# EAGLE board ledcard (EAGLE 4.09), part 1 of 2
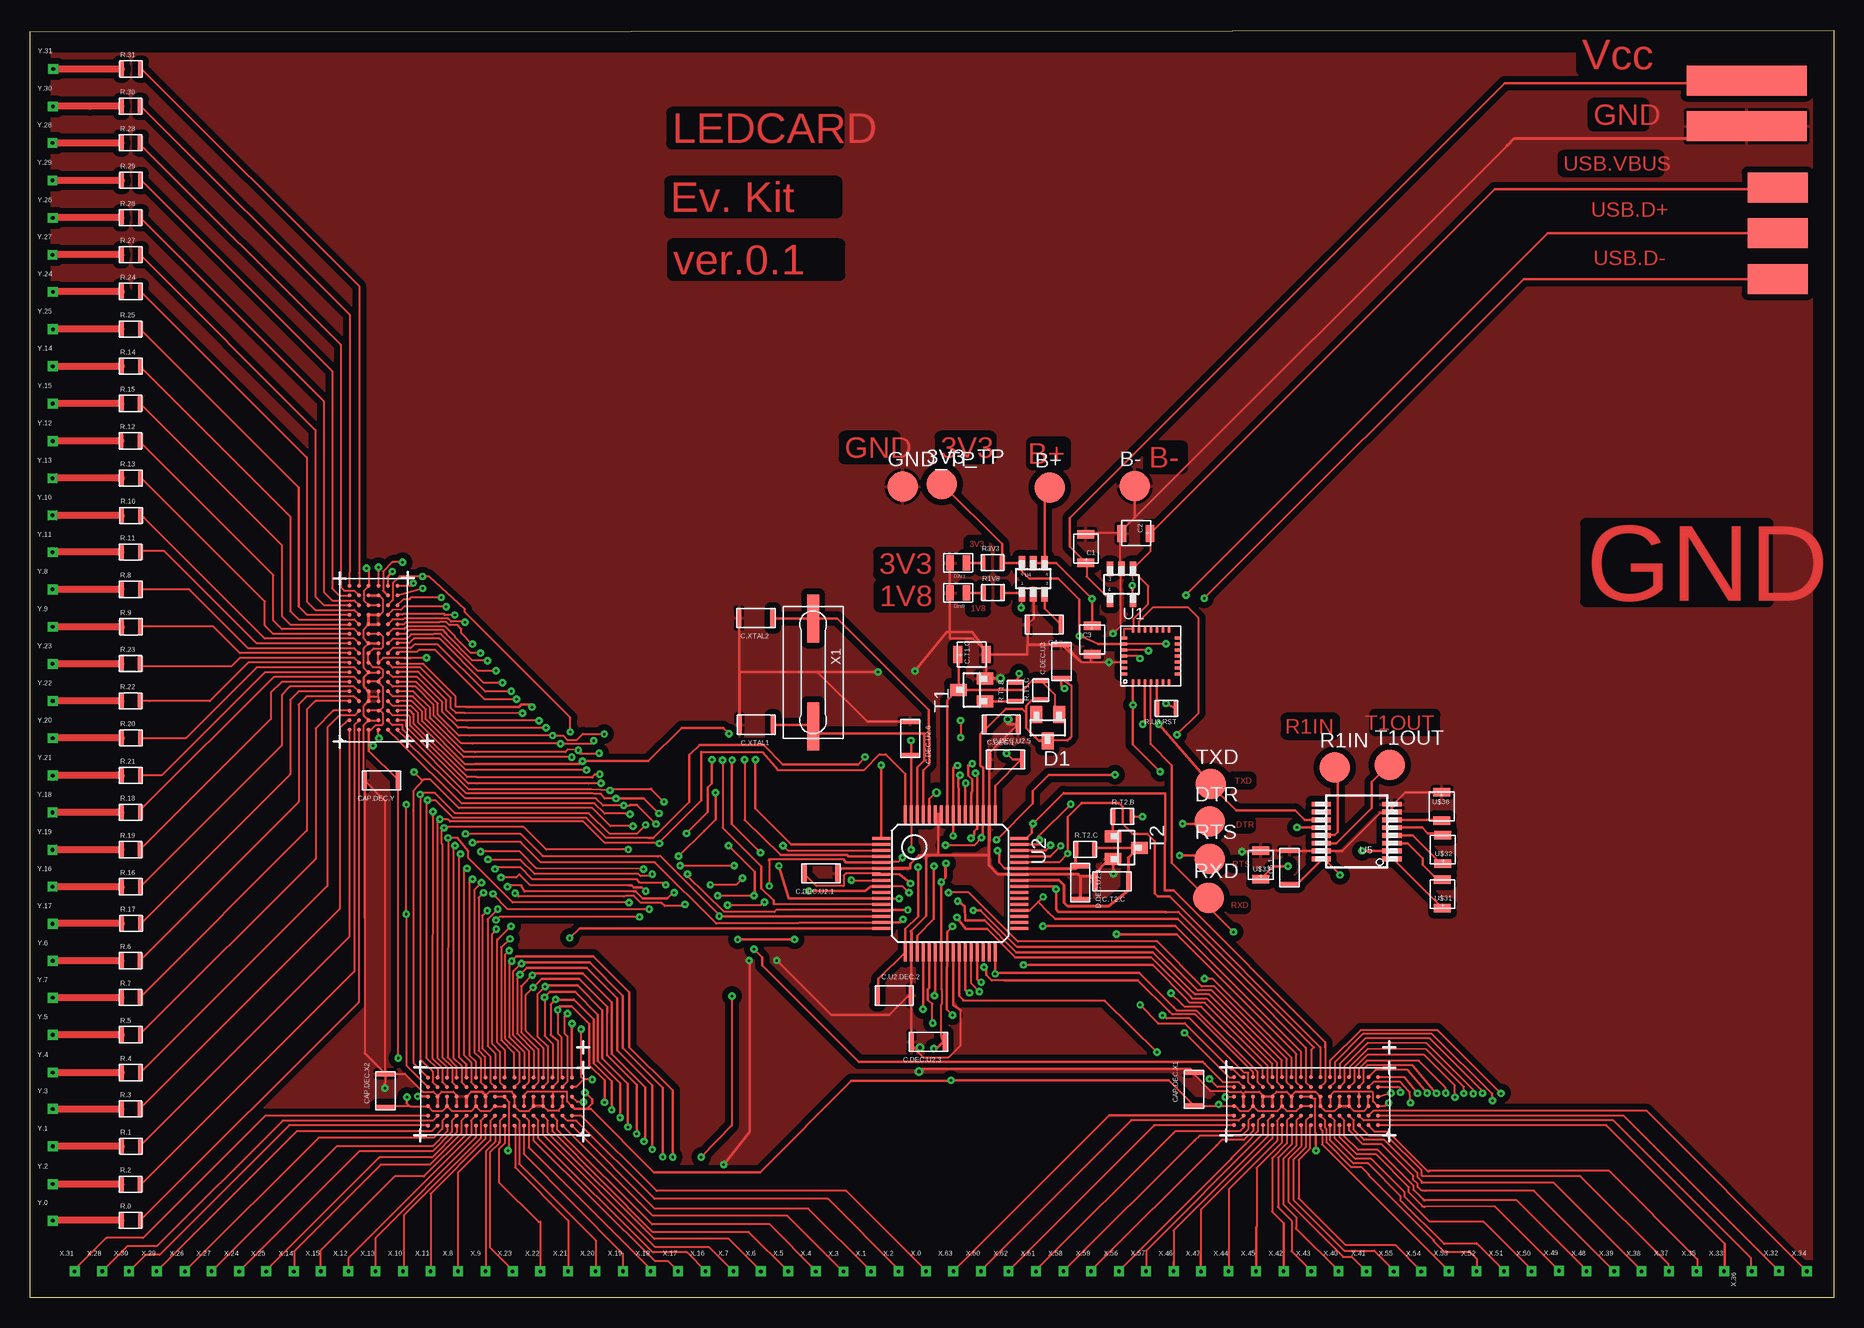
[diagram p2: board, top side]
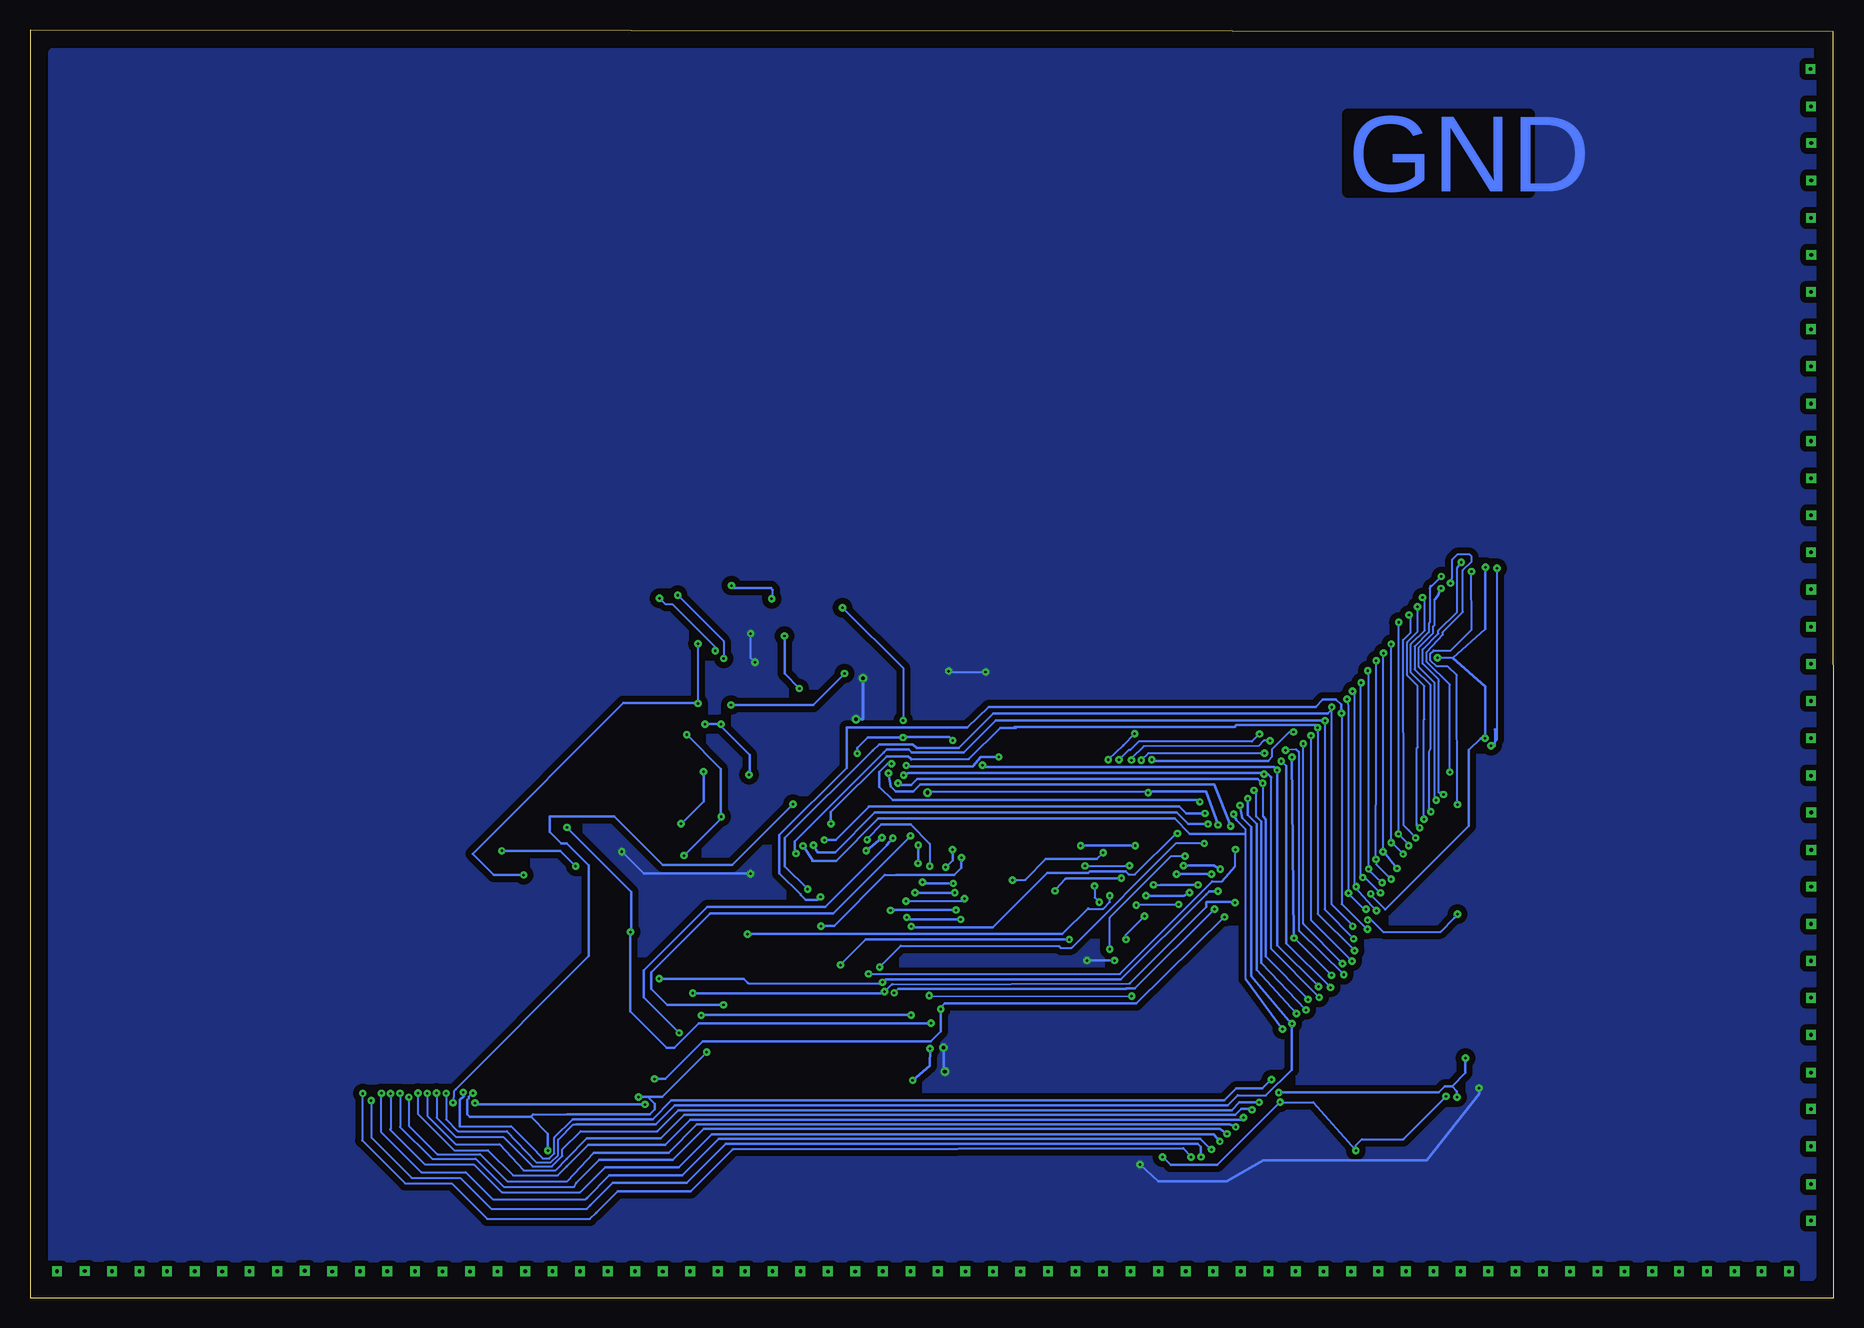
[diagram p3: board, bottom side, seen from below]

Size 150.31 x 105.7 mm. Coordinates in mm from the lower left corner, seen from the top.
Outline: 150.31,0 0,0.01 0.03,105.57 150.31,105.7 150.31,0
Copper layers used: Top, Bottom

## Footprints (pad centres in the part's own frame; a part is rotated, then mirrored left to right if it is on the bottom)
B2,54 = smd 2.54 x 2.54: PP 0,0
CAP_A = smd 1.422 x 0.711: N 0.045,-1.13; P 0.045,1.245
CAP_CERAMIC = smd 1.6 x 0.4: P$1 0,1.22; P$2 0,-1.58
SOT23 = smd 1 x 1.4: 1 -0.95,-1.1; 2 0.95,-1.1; 3 0,1.1
LED_0603 = smd 1.27 x 0.635: P$A 0,-0.7; P$K 0,0.7
USB_CON = smd 5 x 2.5: P$D+ -2.54,1.27; P$D- -2.54,-2.54; P$VCC -2.54,-6.35
SMDR = smd 1.25 x 0.4: P$1 0,0.73; P$2 0,-0.87
SOT23-5 = smd 0.55 x 1.2: 1 -0.95,-1.3; 2 0,-1.3; 3 0.95,-1.3; 4 0.95,1.3; 5 -0.95,1.3
TQFP64 = smd 0.25 x 1.5: 1 -3.75,-5.75; 2 -3.25,-5.75; 3 -2.75,-5.75; 4 -2.25,-5.75; 5 -1.75,-5.75; 6 -1.25,-5.75; 7 -0.75,-5.75; 8 -0.25,-5.75; 9 0.25,-5.75; 10 0.75,-5.75; 11 1.25,-5.75; 12 1.75,-5.75; 13 2.25,-5.75; 14 2.75,-5.75; 15 3.25,-5.75; 16 3.75,-5.75; 33 3.75,5.75; 34 3.25,5.75; 35 2.75,5.75; 36 2.25,5.75; 37 1.75,5.75; 38 1.25,5.75; 39 0.75,5.75; 40 0.25,5.75; 41 -0.25,5.75; 42 -0.75,5.75; 43 -1.25,5.75; 44 -1.75,5.75; 45 -2.25,5.75; 46 -2.75,5.75; 47 -3.25,5.75; 48 -3.75,5.75 | smd 1.5 x 0.25: 17 5.75,-3.75; 18 5.75,-3.25; 19 5.75,-2.75; 20 5.75,-2.25; 21 5.75,-1.75; 22 5.75,-1.25; 23 5.75,-0.75; 24 5.75,-0.25; 25 5.75,0.25; 26 5.75,0.75; 27 5.75,1.25; 28 5.75,1.75; 29 5.75,2.25; 30 5.75,2.75; 31 5.75,3.25; 32 5.75,3.75; 49 -5.75,3.75; 50 -5.75,3.25; 51 -5.75,2.75; 52 -5.75,2.25; 53 -5.75,1.75; 54 -5.75,1.25; 55 -5.75,0.75; 56 -5.75,0.25; 57 -5.75,-0.25; 58 -5.75,-0.75; 59 -5.75,-1.25; 60 -5.75,-1.75; 61 -5.75,-2.25; 62 -5.75,-2.75; 63 -5.75,-3.25; 64 -5.75,-3.75
MLP-28 = smd 0.55 x 0.23: P$1 -2.25,-1.5; P$2 -2.25,-1; P$3 -2.25,-0.5; P$4 -2.25,0; P$5 -2.25,0.5; P$6 -2.25,1; P$7 -2.25,1.5; P$15 2.25,1.5; P$16 2.25,1; P$17 2.25,0.5; P$18 2.25,0; P$19 2.25,-0.5; P$20 2.25,-1; P$21 2.25,-1.5 | smd 0.23 x 0.55: P$8 -1.5,2.25; P$9 -1,2.25; P$10 -0.5,2.25; P$11 0,2.25; P$12 0.5,2.25; P$13 1,2.25; P$14 1.5,2.25; P$22 1.5,-2.25; P$23 1,-2.25; P$24 0.5,-2.25; P$25 0,-2.25; P$26 -0.5,-2.25; P$27 -1,-2.25; P$28 -1.5,-2.25
SOT-23_RT6 = smd 0.55 x 1.2: 1 -0.95,-1.3; 2 0,-1.3; 3 0.95,-1.3; 4 0.95,1.3; 5 0,1.3; 6 -0.95,1.3
TSOP16 = smd 0.4 x 1.6: 1 -2.275,-2.79; 2 -1.625,-2.79; 3 -0.975,-2.79; 4 -0.325,-2.79; 5 0.325,-2.79; 6 0.975,-2.79; 7 1.625,-2.79; 8 2.275,-2.79; 9 2.275,3.11; 10 1.625,3.11; 11 0.975,3.11; 12 0.325,3.11; 13 -0.325,3.11; 14 -0.975,3.11; 15 -1.625,3.11; 16 -2.275,3.11
PIN2 = smd 10 x 2.5: P$1 1.27,0; P$2 1.27,-3.81
LFBGA96 = smd 0.35 x 0.35: P$A1 -2,-6.054; P$A2 -1.2,-6.054; P$A3 -0.4,-6.054; P$A4 0.4,-6.054; P$A5 1.2,-6.054; P$A6 2,-6.054; P$B1 -2,-5.254; P$B2 -1.2,-5.254; P$B3 -0.4,-5.254; P$B4 0.4,-5.254; P$B5 1.2,-5.254; P$B6 2,-5.254; P$C1 -2,-4.454; P$C2 -1.2,-4.454; P$C3 -0.4,-4.454; P$C4 0.4,-4.454; P$C5 1.2,-4.454; P$C6 2,-4.454; P$D1 -2,-3.654; P$D2 -1.2,-3.654; P$D3 -0.4,-3.654; P$D4 0.4,-3.654; P$D5 1.2,-3.654; P$D6 2,-3.654; P$E1 -2,-2.854; P$E2 -1.2,-2.854; P$E3 -0.4,-2.854; P$E4 0.4,-2.854; P$E5 1.2,-2.854; P$E6 2,-2.854; P$F1 -2,-2.054; P$F2 -1.2,-2.054; P$F3 -0.4,-2.054; P$F4 0.4,-2.054; P$F5 1.2,-2.054; P$F6 2,-2.054; P$G1 -2,-1.254; P$G2 -1.2,-1.254; P$G3 -0.4,-1.254; P$G4 0.4,-1.254; P$G5 1.2,-1.254; P$G6 2,-1.254; P$H1 -2,-0.454; P$H2 -1.2,-0.454; P$H3 -0.4,-0.454; P$H4 0.4,-0.454; P$H5 1.2,-0.454; P$H6 2,-0.454; P$J1 -2,0.346; P$J2 -1.2,0.346; P$J3 -0.4,0.346; P$J4 0.4,0.346; P$J5 1.2,0.346; P$J6 2,0.346; P$K1 -2,1.146; P$K2 -1.2,1.146; P$K3 -0.4,1.146; P$K4 0.4,1.146; P$K5 1.2,1.146; P$K6 2,1.146; P$L1 -2,1.946; P$L2 -1.2,1.946; P$L3 -0.4,1.946; P$L4 0.4,1.946; P$L5 1.2,1.946; P$L6 2,1.946; P$M1 -2,2.746; P$M2 -1.2,2.746; P$M3 -0.4,2.746; P$M4 0.4,2.746; P$M5 1.2,2.746; P$M6 2,2.746; P$N1 -2,3.546; P$N2 -1.2,3.546; P$N3 -0.4,3.546; P$N4 0.4,3.546; P$N5 1.2,3.546; P$N6 2,3.546; P$P1 -2,4.346; P$P2 -1.2,4.346; P$P3 -0.4,4.346; P$P4 0.4,4.346; P$P5 1.2,4.346; P$P6 2,4.346; P$R1 -2,5.146; P$R2 -1.2,5.146; P$R3 -0.4,5.146; P$R4 0.4,5.146; P$R5 1.2,5.146; P$R6 2,5.146; P$T1 -2,5.946; P$T2 -1.2,5.946; P$T3 -0.4,5.946; P$T4 0.4,5.946; P$T5 1.2,5.946; P$T6 2,5.946
XTAL = smd 1 x 4: P$1 0,4.5; P$2 0,-4.5
PAD0.012 = drill 0.305 pad 0.305 square: P$ 0,0

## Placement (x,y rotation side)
3V3_TP  B2,54  [B2,54]  75.98,67.86 0 top
B+  B2,54  [B2,54]  84.99,67.56 0 top
B-  B2,54  [B2,54]  92.05,67.68 0 top
C1  10uF  [CAP_A]  88.03,62.54 180 top
C2  10uF  [CAP_A]  92.11,63.79 270 top
C3  10uF  [CAP_A]  88.48,54.81 0 top
C4  10uF  [CAP_CERAMIC]  84.33,56.14 90 top
C.DEC.1  100nF  [CAP_CERAMIC]  80.76,47.81 90 top
C.DEC.U2.1  100nF  [CAP_CERAMIC]  65.73,35.39 90 top
C.DEC.U2.3  100nF  [CAP_CERAMIC]  74.68,21.36 90 top
C.DEC.U2.5  100nF  [CAP_CERAMIC]  81.48,44.89 270 top
C.DEC.U2.6  100n  [CAP_CERAMIC]  73.36,46.46 180 top
C.DEC.U3  0.1uF  [CAP_CERAMIC]  85.95,53.24 0 top
C.T1.C  10uF  [CAP_A]  78.56,53.61 90 top
C.T2.C  100n  [CAP_CERAMIC]  89.98,34.74 90 top
C.U2.DEC.2  100nF  [CAP_CERAMIC]  72.21,25.21 270 top
C.U5.1  100nF  [CAP_CERAMIC]  104.96,36.06 0 top
C.XTAL1  22pF  [CAP_CERAMIC]  60.33,47.79 90 top
C.XTAL2  22pF  [CAP_CERAMIC]  60.31,56.69 90 top
CAP.DEC.X1  100Nf  [CAP_CERAMIC]  97.01,17.59 0 top
CAP.DEC.X2  100nF  [CAP_CERAMIC]  29.63,17.47 0 top
CAP.DEC.Y  100nF  [CAP_CERAMIC]  29.1,43.15 90 top
D1  BAS40TTOP  [SOT23]  84.81,47.54 180 top
D1V8  red  [LED_0603]  77.35,58.78 90 top
D3V3  green  [LED_0603]  77.35,61.28 90 top
D.DEC.U2.4  100nF  [CAP_CERAMIC]  87.53,34.44 180 top
DTR  B2,54  [B2,54]  98.31,39.72 0 top
GND_TP  B2,54  [B2,54]  72.73,67.66 0 top
K1  USB_CON_PCB  [USB_CON]  143.1,86.21 180 top
R1IN  B2,54  [B2,54]  108.72,44.22 0 top
R1V8  180  [SMDR]  80.31,58.78 270 top
R3V3  250  [SMDR]  80.28,61.28 270 top
R.0  150  [SMDR]  8.47,6.46 270 top
R.1  150  [SMDR]  8.49,12.63 270 top
R.2  150  [SMDR]  8.46,9.47 270 top
R.3  150  [SMDR]  8.47,15.74 270 top
R.4  150  [SMDR]  8.48,18.77 270 top
R.5  150  [SMDR]  8.48,21.93 270 top
R.6  150  [SMDR]  8.46,28.1 270 top
R.7  150  [SMDR]  8.47,25.04 270 top
R.8  150  [SMDR]  8.47,59.07 270 top
R.9  150  [SMDR]  8.48,55.93 270 top
R.10  150  [SMDR]  8.5,65.22 270 top
R.11  150  [SMDR]  8.47,62.16 270 top
R.12  150  [SMDR]  8.46,71.44 270 top
R.13  150  [SMDR]  8.47,68.33 270 top
R.14  150  [SMDR]  8.48,77.66 270 top
R.15  150  [SMDR]  8.47,74.56 270 top
R.16  150  [SMDR]  8.48,34.26 270 top
R.17  150  [SMDR]  8.49,31.21 270 top
R.18  150  [SMDR]  8.47,40.46 270 top
R.19  150  [SMDR]  8.47,37.36 270 top
R.20  150  [SMDR]  8.48,46.68 270 top
R.21  150  [SMDR]  8.48,43.54 270 top
R.22  150  [SMDR]  8.47,49.76 270 top
R.23  150  [SMDR]  8.47,52.87 270 top
R.24  150  [SMDR]  8.48,83.89 270 top
R.25  150  [SMDR]  8.47,80.75 270 top
R.26  150  [SMDR]  8.47,90.04 270 top
R.27  150  [SMDR]  8.47,86.97 270 top
R.28  150  [SMDR]  8.47,96.28 270 top
R.29  150  [SMDR]  8.49,93.16 270 top
R.30  150  [SMDR]  8.47,99.34 270 top
R.31  150  [SMDR]  8.48,102.45 270 top
R.T1.B  33k  [SMDR]  82.11,50.61 0 top
R.T1.C  10k  [SMDR]  84.23,50.74 0 top
R.T2.B  33k  [SMDR]  91.11,40.14 270 top
R.T2.C  10k  [SMDR]  88.01,37.39 270 top
R.U3.RST  4k7  [SMDR]  94.63,49.16 90 top
RTS  B2,54  [B2,54]  98.31,36.59 0 top
RXD  B2,54  [B2,54]  98.21,33.34 0 top
T1  2N3904TOP  [SOT23]  78.48,50.69 90 top
T1OUT  B2,54  [B2,54]  113.32,44.44 0 top
T2  2N3904TOP  [SOT23]  91.36,37.54 270 top
TXD  B2,54  [B2,54]  98.41,42.84 0 top
U1  MAX1555  [SOT23-5]  90.96,59.49 180 top
U2  LPC21X4  [TQFP64]  76.67,34.58 270 top
U3  CP2101  [MLP-28]  93.41,53.51 0 top
U4  MAX8882TOP  [SOT-23_RT6]  83.61,59.96 0 top
U5  MAX3232  [TSOP16]  110.7,38.88 90 top
U$3  PIN2  [PIN2]  144.32,97.67 180 top
U$31  0.1uF  [CAP_A]  117.74,33.73 180 top
U$32  470nF/TNT  [CAP_A]  117.77,37.44 180 top
U$33  470nF/TNT  [CAP_A]  102.59,36.16 180 top
U$36  CAP_A  [CAP_A]  117.61,40.9 0 top
U.X1  74LVT32374  [LFBGA96]  39.11,16.39 90 top
U.X2  74LVT32374  [LFBGA96]  106.28,16.39 90 top
U.Y  74LVT32374  [LFBGA96]  28.62,53.41 0 top
X1  8MHz  [XTAL]  65.26,52.16 180 top
X.0  PAD_PIN  [PAD0.012]  74.66,2.23 0 top
X.1  PAD_PIN  [PAD0.012]  70.07,2.22 0 top
X.2  PAD_PIN  [PAD0.012]  72.37,2.22 0 top
X.3  PAD_PIN  [PAD0.012]  67.79,2.2 0 top
X.4  PAD_PIN  [PAD0.012]  65.48,2.22 0 top
X.5  PAD_PIN  [PAD0.012]  63.19,2.23 0 top
X.6  PAD_PIN  [PAD0.012]  60.89,2.22 0 top
X.7  PAD_PIN  [PAD0.012]  58.61,2.22 0 top
X.8  PAD_PIN  [PAD0.012]  35.66,2.22 0 top
X.9  PAD_PIN  [PAD0.012]  37.96,2.22 0 top
X.10  PAD_PIN  [PAD0.012]  31.09,2.22 0 top
X.11  PAD_PIN  [PAD0.012]  33.37,2.22 0 top
X.12  PAD_PIN  [PAD0.012]  26.53,2.23 0 top
X.13  PAD_PIN  [PAD0.012]  28.79,2.22 0 top
X.14  PAD_PIN  [PAD0.012]  21.98,2.21 0 top
X.15  PAD_PIN  [PAD0.012]  24.22,2.22 0 top
X.16  PAD_PIN  [PAD0.012]  56.29,2.22 0 top
X.17  PAD_PIN  [PAD0.012]  54,2.23 0 top
X.18  PAD_PIN  [PAD0.012]  51.72,2.22 0 top
X.19  PAD_PIN  [PAD0.012]  49.41,2.23 0 top
X.20  PAD_PIN  [PAD0.012]  47.11,2.23 0 top
X.21  PAD_PIN  [PAD0.012]  44.84,2.22 0 top
X.22  PAD_PIN  [PAD0.012]  42.53,2.22 0 top
X.23  PAD_PIN  [PAD0.012]  40.22,2.22 0 top
X.24  PAD_PIN  [PAD0.012]  17.44,2.22 0 top
X.25  PAD_PIN  [PAD0.012]  19.68,2.21 0 top
X.26  PAD_PIN  [PAD0.012]  12.9,2.22 0 top
X.27  PAD_PIN  [PAD0.012]  15.13,2.22 0 top
X.28  PAD_PIN  [PAD0.012]  6.02,2.22 0 top
X.29  PAD_PIN  [PAD0.012]  10.55,2.22 0 top
X.30  PAD_PIN  [PAD0.012]  8.26,2.23 0 top
X.31  PAD_PIN  [PAD0.012]  3.72,2.22 0 top
X.32  PAD_PIN  [PAD0.012]  145.75,2.24 0 top
X.33  PAD_PIN  [PAD0.012]  141.18,2.22 0 top
X.34  PAD_PIN  [PAD0.012]  148.07,2.22 0 top
X.35  PAD_PIN  [PAD0.012]  138.89,2.22 0 top
X.36  PAD_PIN  [PAD0.012]  143.48,2.22 90 top
X.37  PAD_PIN  [PAD0.012]  136.59,2.22 0 top
X.38  PAD_PIN  [PAD0.012]  134.29,2.22 0 top
X.39  PAD_PIN  [PAD0.012]  132.02,2.22 0 top
X.40  PAD_PIN  [PAD0.012]  109.05,2.23 0 top
X.41  PAD_PIN  [PAD0.012]  111.36,2.22 0 top
X.42  PAD_PIN  [PAD0.012]  104.47,2.22 0 top
X.43  PAD_PIN  [PAD0.012]  106.77,2.23 0 top
X.44  PAD_PIN  [PAD0.012]  99.88,2.22 0 top
X.45  PAD_PIN  [PAD0.012]  102.17,2.22 0 top
X.46  PAD_PIN  [PAD0.012]  95.3,2.22 0 top
X.47  PAD_PIN  [PAD0.012]  97.58,2.21 0 top
X.48  PAD_PIN  [PAD0.012]  129.7,2.23 0 top
X.49  PAD_PIN  [PAD0.012]  127.41,2.26 0 top
X.50  PAD_PIN  [PAD0.012]  125.13,2.22 0 top
X.51  PAD_PIN  [PAD0.012]  122.82,2.23 0 top
X.52  PAD_PIN  [PAD0.012]  120.54,2.22 0 top
X.53  PAD_PIN  [PAD0.012]  118.24,2.23 0 top
X.54  PAD_PIN  [PAD0.012]  115.94,2.21 0 top
X.55  PAD_PIN  [PAD0.012]  113.65,2.21 0 top
X.56  PAD_PIN  [PAD0.012]  90.74,2.22 0 top
X.57  PAD_PIN  [PAD0.012]  93,2.23 0 top
X.58  PAD_PIN  [PAD0.012]  86.12,2.22 0 top
X.59  PAD_PIN  [PAD0.012]  88.43,2.22 0 top
X.60  PAD_PIN  [PAD0.012]  79.25,2.22 0 top
X.61  PAD_PIN  [PAD0.012]  83.83,2.21 0 top
X.62  PAD_PIN  [PAD0.012]  81.55,2.21 0 top
X.63  PAD_PIN  [PAD0.012]  76.95,2.22 0 top
Y.0  PAD_PIN  [PAD0.012]  1.9,6.44 0 top
Y.1  PAD_PIN  [PAD0.012]  1.89,12.64 0 top
Y.2  PAD_PIN  [PAD0.012]  1.89,9.48 0 top
Y.3  PAD_PIN  [PAD0.012]  1.89,15.76 0 top
Y.4  PAD_PIN  [PAD0.012]  1.89,18.78 0 top
Y.5  PAD_PIN  [PAD0.012]  1.89,21.94 0 top
Y.6  PAD_PIN  [PAD0.012]  1.89,28.09 0 top
Y.7  PAD_PIN  [PAD0.012]  1.89,25.02 0 top
Y.8  PAD_PIN  [PAD0.012]  1.89,59.07 0 top
Y.9  PAD_PIN  [PAD0.012]  1.89,55.95 0 top
Y.10  PAD_PIN  [PAD0.012]  1.88,65.25 0 top
Y.11  PAD_PIN  [PAD0.012]  1.89,62.15 0 top
Y.12  PAD_PIN  [PAD0.012]  1.89,71.44 0 top
Y.13  PAD_PIN  [PAD0.012]  1.88,68.33 0 top
Y.14  PAD_PIN  [PAD0.012]  1.9,77.67 0 top
Y.15  PAD_PIN  [PAD0.012]  1.9,74.55 0 top
Y.16  PAD_PIN  [PAD0.012]  1.88,34.28 0 top
Y.17  PAD_PIN  [PAD0.012]  1.89,31.18 0 top
Y.18  PAD_PIN  [PAD0.012]  1.88,40.47 0 top
Y.19  PAD_PIN  [PAD0.012]  1.88,37.36 0 top
Y.20  PAD_PIN  [PAD0.012]  1.9,46.66 0 top
Y.21  PAD_PIN  [PAD0.012]  1.89,43.55 0 top
Y.22  PAD_PIN  [PAD0.012]  1.89,49.77 0 top
Y.23  PAD_PIN  [PAD0.012]  1.89,52.86 0 top
Y.24  PAD_PIN  [PAD0.012]  1.9,83.88 0 top
Y.25  PAD_PIN  [PAD0.012]  1.9,80.76 0 top
Y.26  PAD_PIN  [PAD0.012]  1.9,90.05 0 top
Y.27  PAD_PIN  [PAD0.012]  1.88,86.96 0 top
Y.28  PAD_PIN  [PAD0.012]  1.88,96.28 0 top
Y.29  PAD_PIN  [PAD0.012]  1.88,93.17 0 top
Y.30  PAD_PIN  [PAD0.012]  1.9,99.33 0 top
Y.31  PAD_PIN  [PAD0.012]  1.93,102.46 0 top

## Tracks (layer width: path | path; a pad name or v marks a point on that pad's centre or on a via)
1V8  (via drill 0.2)
  Top 0.15: U2.63 | 73.43,40.32 v73.43,37.38
  Top 0.17: v77.55,48.14 v77.56,46.72 | U4.1 82.66,58.59 82.68,58.56 82.66,58.54 v82.6,57.54
  Top 0.2: C.DEC.U2.5.P$1 82.68,44.86 82.65,44.86 82.62,44.88 | C.U2.DEC.2.P$2 70.65,25.19 70.68,25.19 70.68,26.58 U2.17 72.92,30.75 74.01,31.81 v74.01,35.91 | 73.36,45.31 73.33,45.31 | 73.36,45.31 C.DEC.U2.6.P$1 | 73.36,45.31 73.42,45.31 U2.63 73.43,40.32 | v73.42,46.47 73.43,45.69 U2.63 | U4.1 82.59,58.66 82.47,58.78 R1V8.P$1 | v81.38,45.39 81.89,44.88 82.62,44.88 | 82.62,44.88 82.68,44.88 | U2.49 80.42,42.68 82.62,44.88
  Bottom 0.17: v77.55,48.14 77.56,52.54 v82.6,57.54
  Bottom 0.2: v74.01,35.91 73.43,36.49 v73.43,37.38 | v73.42,46.47 73.72,46.77 77.55,46.77 77.58,46.74 77.57,46.73 | v77.56,46.73 v77.54,46.73 | 77.57,46.73 80.5,46.73 81.39,45.84 81.39,45.38 | v77.56,46.73 77.57,46.73 | v77.56,46.72 v77.56,46.73 | 81.39,45.38 81.39,45.36 | 81.39,45.38 v81.38,45.39
3V3  (via drill 0.2)
  Top 0.15: 29.13,48.96 29.43,49.26 29.43,50.93 29.02,51.34 U.Y.P$F4 29,51.34 28.97,51.37 28.91,51.37 | 30.67,43.21 30.68,43.21 | 30.67,43.21 CAP.DEC.Y.P$2 v30.69,19.99 | 28.23,45.61 30.63,43.21 30.67,43.21 | 31.66,15.99 31.66,16.01 31.68,15.99 U.X1.P$T3 33.18,15.97 33.18,15.96 33.53,15.59 34.39,15.59 34.76,15.96 U.X1.P$P3 | 31.41,16.21 31.66,15.96 31.66,15.98 31.66,15.99 | CAP.DEC.X2.P$2 29.73,15.99 31.66,15.99 | U.X2.P$P3 U.X2.P$P4 | v113.23,16.26 112.93,16.01 112.75,15.99 U.X2.P$A3 111.93,16.38 111.93,17.08 111.83,17.19 110.79,17.19 110.73,17.13 110.73,17.12 110.74,17.11 | 96.64,16.03 98.77,16.03 | C.DEC.U2.1.P$1 64.48,35.39 65.53,34.34 67.81,34.34 67.81,35.21 67.98,35.39 70.87,35.39 U2.7 72.49,35.33 | 76.12,21.36 75.99,21.24 | v76.76,18.14 76.68,18.29 | 34.78,16.77 U.X1.P$P4 34.76,16.01 34.76,16 U.X1.P$P3 | U.X1.P$L3 U.X1.P$L4 | U.X2.P$F3 | U.X2.P$F3 108.36,15.99 | 110.74,17.11 110.76,17.13 110.76,17.19 108.66,17.19 108.33,16.82 U.X2.P$F4 | U.Y.P$C4 U.Y.P$C3 | U.Y.P$C4 29.05,48.96 | 29.13,48.96 29.13,48.97 29.12,48.98 29.1,48.96 U.Y.P$C4 | U.Y.P$A3 28.41,47.36 28.83,47.76 29.35,47.76 29.43,47.87 29.43,48.72 29.2,48.96 29.2,48.97 29.19,48.98 29.17,48.96 29.13,48.96 | 28.21,51.37 28.2,51.37 | 28.21,51.37 U.Y.P$F3 | 28.91,51.37 29.42,51.86 29.43,52.31 29.16,52.56 28.62,52.56 U.Y.P$H3 28.18,53 28.18,53.72 U.Y.P$J3 28.63,54.16 29.33,54.16 29.43,54.26 29.43,55.11 29.18,55.36 29.14,55.36 | 28.91,51.37 28.21,51.37 | 29.14,55.36 | 29.14,55.36 29,55.36 | 29,55.36 U.Y.P$L4 U.Y.P$L3 | 29,55.36 28.2,55.36 | U.Y.P$L3 | U.Y.P$L3 | 28.22,59.34 U.Y.P$T3 | 28.22,59.34 27.82,58.94 27.82,58.16 U.Y.P$P3 28.25,57.76 28.26,57.75 28.27,57.76 U.Y.P$P4
  Top 0.15: 28.22,59.34 28.22,60.66 v28.05,60.83 | U.X2.P$P3 101.9,15.99 | U.X2.P$P3 | U.X2.P$P3 101.95,15.99 102.33,15.6 103.97,15.6 104.33,15.97 U.X2.P$L3 | U.X2.P$P3 101.57,15.6 100.8,15.6 100.47,15.98 100.32,15.98 | 100.32,15.98 100.3,15.98 | 100.32,15.98 U.X2.P$T3 100.31,16.02 98.82,16.02 | 98.76,16.02 98.75,16.02 | 98.77,16.03 98.76,16.02 | v99.06,16.14 98.94,16.02 98.82,16.02 | 98.76,16.02 98.82,16.02 | 98.82,16.02 98.77,16.02 98.77,16.03 | 80.76,37.26 80.71,37.26 | v80.63,37.29 80.63,37.26 80.76,37.26 | 80.76,37.26 80.76,37.29 | U.X1.P$F4 U.X1.P$F3 41.16,16.88 41.45,17.19 43.55,17.19 43.56,17.18 | U.X1.P$H3 U.X1.P$J3 38.75,15.98 38.35,15.58 37.53,15.58 37.14,15.97 | U.X1.P$A3 44.77,16.38 44.77,17.19 43.56,17.19 43.56,17.18 | 43.56,17.18 U.X1.P$C3 U.X1.P$C4 | U.X1.P$P3 35.15,15.59 36.81,15.59 37.14,15.97 | 37.14,15.97 U.X1.P$L3 | 37.16,15.96 | 37.16,15.96 U.X1.P$L3 | 37.14,15.97 37.16,15.97 37.16,15.96 | U.X2.P$C4 110.72,16.8 110.74,16.83 110.74,17.11 | U.X2.P$C4 | 110.73,15.97 U.X2.P$C3 | U.X2.P$C4 110.73,15.97 | 110.73,15.97 110.74,15.97 | U.X2.P$F3 108.34,15.98 | U.X2.P$F3 | U.X2.P$F3 U.X2.P$F4 108.34,16.79 U.X2.P$F4 | U.X2.P$F4 108.34,16.77 | U.X2.P$L3 U.X2.P$L4 | U.X2.P$L3 | U.X2.P$L3 104.72,15.6 105.54,15.6 105.89,15.95 105.93,15.95 U.X2.P$J3 105.94,16.01 106.72,16.01 U.X2.P$H3 | U2.23 75.92,25.76 75.99,25.7 75.99,24.49 75.92,24.41 75.92,21.91 75.96,21.86 75.94,21.84 75.92,21.84
  Top 0.17: C.DEC.U3.P$2 86.78,51.06 86.78,46.81 86.46,46.49 | 86.46,46.49 86.43,46.46 84.68,46.46 | 89.04,54.51 87.41,55.22 | C.DEC.U3.P$2 86.21,51.66 86.26,51.61 86.11,51.46 | C.DEC.U3.P$2 86.18,51.61 86.76,51.04 86.76,46.79 86.46,46.49 | 86.46,46.49 84.03,46.49 83.03,47.49 83.03,49.39 83.68,50.04 84.06,50.04 R.T1.C.P$2 | v87.43,55.18 87.44,55.11 v87.44,55.18 87.41,55.22 | v94.66,49.56 94.65,49.51 | 90.08,54.51 90.04,54.51 U3.P$6 | 82.66,60.59 U4.6 | U3.P$6 | U3.P$6 94.64,54.51 v94.66,54.54 | 87.41,55.22 87.41,55.15 | v87.43,55.18 87.48,55.16 | 87.41,55.22 v87.43,55.18 | v79.3,38.38 78.67,37.74 v76.29,37.74
  Top 0.2: U.X1.P$A3 45.39,15.76 46.41,15.76 | 46.41,15.76 46.86,16.21 46.86,16.55 46.28,17.12 v46.25,17.12 | v31.41,16.74 31.41,16.21 | 79.54,47.37 C.DEC.1.P$1 | 79.54,47.37 79.18,47.01 79.18,44.41 79.42,44.17 U2.51 79.41,40.3 79.41,38.66 v79.3,38.38 | D1.3 84.11,46.44 83.01,47.54 | 83.01,47.54 83.01,49.36 83.61,49.96 84.16,49.96 84.23,49.89 R.T1.C.P$2 | 83.01,47.54 83.01,48.79 82.68,49.11 81.31,49.11 79.56,47.37 79.54,47.37 | C.DEC.U2.3.P$2 76.12,21.36 75.92,21.84 | CAP.DEC.X1.P$2 94.88,18.14 v76.76,18.14 | 76.68,18.29 76.68,18.06 76.31,18.09 68.46,18.09 60.86,10.49 52.88,10.49 52.89,10.48 | v73.38,34.56 72.49,35.33 | U2.43 81.24,35.83 80.76,36.31 80.76,37.29 | U3.P$6 89.04,54.51 | 94.65,49.51 R.U3.RST.P$2 | 82.66,60.59 83.28,59.96 85.68,59.96 87.43,58.21 v87.43,55.18 | 76.32,35.12 v76.32,36.23 76.27,36.32 76.27,35 v75.94,34.67 75.94,34.63 75.92,34.63 | U4.6 81.04,61.26 81.02,61.24 81.01,61.25 R3V3.P$1 81.01,62.83 3V3_TP.PP | 75.92,34.63 U2.23 | 75.92,34.63 | U5.16 107.59,36.48 105.59,34.48 C.U5.1.P$2 105.58,34.48 107.64,36.54 107.89,36.54 v109.17,35.26 | 46.41,15.76 46.71,15.76 51.99,10.48 52.89,10.48 | 52.89,10.48 52.9,10.48 | 28.23,46.04 v28.57,46.03 28.22,46.03 U.Y.P$A3 | 28.23,46.04 U.Y.P$A3 | 28.23,45.61 28.23,46.04 | U.Y.P$A3 | C.DEC.U3.P$2 85.95,51.06 v86.2,50.81
  Top 0.254: D.DEC.U2.4.P$2 87.5,36.02 87.43,36.09 87.17,35.83 | U2.43 87.17,35.83 | 87.17,35.83 87.06,35.94 87.14,36.02 R.T2.C.P$2 | 96.64,16.03 97.06,16.01 CAP.DEC.X1.P$2
  Top 0.27: v75.31,20.8 75.33,20.81 75.57,20.81 75.99,21.24
  Bottom 0.15: v28.05,60.83 28.05,46.54 v28.56,46.03
  Bottom 0.17: v94.66,54.54 v94.66,49.56 94.66,49.46 94.61,49.41 | 76.29,36.32 v76.32,36.23
  Bottom 0.2: 28.22,46.76 28.23,46.04 28.23,46.03 28.24,46.02 28.25,46.03 v28.56,46.03 v28.57,46.03 28.22,46.38 28.22,47.38 28.23,47.39 28.21,47.41 | v31.41,16.74 31.41,17.11 31.41,17.12 31.41,17.24 31.81,17.64 | v76.76,18.14 75.33,19.34 v75.31,20.8 | v79.3,38.38 v80.63,37.29 | v76.29,37.74 76.29,36.32 | v113.23,16.26 113.23,16.24 113.13,16.14 v99.06,16.14 | v73.37,34.55 73.32,34.55 | v73.37,34.55 v73.38,34.56 | v75.94,34.67 75.83,34.55 v73.37,34.55 | v109.17,35.26 111.67,35.26 113.43,37.02 100.87,49.58 94.68,49.58 v94.66,49.56 | 31.81,17.64 31.81,17.63 32.44,17.63 32.91,17.16 46.21,17.16 v46.25,17.12 | v30.69,19.99 30.69,18.75 31.81,17.64 | v86.2,50.81 87.43,52.04 v87.43,55.18
B$COM.DTR  (via drill 0.2)
  Top 0.15: 98.43,39.31 98.48,39.26 | 98.43,39.31 DTR.PP | 98.21,39.54 98.43,39.31
  Top 0.17: R.T1.B.P$1 82.45,51.91 v82.43,52.06 | U3.P$28 v91.91,49.44
  Top 0.2: U3.P$28 91.91,46.13 v94.18,43.86 | v96.06,39.54 98.21,39.54
  Bottom 0.2: v94.18,43.86 94.18,41.41 v96.06,39.54 | v82.43,52.06 85.06,49.44 v91.91,49.44
B$COM.RTS  (via drill 0.2)
  Top 0.15: 98.01,36.89 RTS.PP | 91.81,40.11 R.T2.B.P$1
  Top 0.17: U3.P$9 92.41,56.39 93.58,57.56 96.51,57.56 97.36,56.71 97.36,48.74 v95.58,46.96 | 91.78,40.11 91.81,40.11 v92.71,40.11
  Top 0.2: v95.81,36.89 98.01,36.89
  Bottom 0.17: 92.76,40.14 92.76,39.94 | 92.76,40.14 92.76,40.16 92.78,40.14 | 92.76,40.14 92.73,40.14 v92.71,40.11 | 92.76,40.14 92.78,40.14 | 92.78,40.14 92.81,40.11
  Bottom 0.2: 92.76,39.94 v95.81,36.89 | v95.58,46.96 92.73,44.11 92.73,40.14
B$COM.RXD  (via drill 0.2)
  Top 0.15: 75.21,24.51 75.21,22.74 v75.23,22.91 | RXD.PP 98.03,33.51 97.91,33.51 97.91,32.89 | U3.P$25 93.38,51.16 93.38,46.2
  Top 0.2: U2.21 74.92,25.86 74.8,25.74 74.8,24.85 75.21,24.51 | v100.28,30.51 97.91,32.89 | 97.91,33.51 95.16,36.26 95.16,44.41 93.38,46.2 | U5.12 107.58,39.22 v105.57,39.22
  Bottom 0.2: v105.57,39.22 100.21,33.86 100.21,30.63 100.27,30.57 v100.27,30.5 v100.28,30.51 100.28,23.89 97.26,20.86 96.64,20.86 94.59,22.91 v75.23,22.91
B$COM.TXD  (via drill 0.2)
  Top 0.15: 92.9,51.24 U3.P$26
  Top 0.2: v94.07,47.84 TXD.PP 98.3,42.84 | U2.19 73.92,30.18 75.33,31.59 v75.33,35.99 | v80.55,38.19 83.58,41.24 83.58,42.29 84.91,43.61 v90.41,43.61 | U5.11 106.22,39.86 105.45,40.62 100.51,40.62 98.3,42.84 | 98.3,42.84 98.26,42.87 | v92.73,47.83 v92.74,47.83 92.9,47.99 92.9,51.24
  Bottom 0.17: 75.33,37.86 v75.33,35.99 | 79.36,39.46 80.51,38.31 v80.55,38.19
  Bottom 0.2: 75.33,37.86 76.93,39.46 79.36,39.46 | 92.93,47.84 92.88,47.84 | v90.41,43.61 90.38,43.58 90.35,43.58 90.35,45.27 92.93,47.84 | 92.93,47.84 v92.73,47.83 92.93,47.85 93.84,47.85 v94.07,47.84
B$I.0  (via drill 0.2)
  Top 0.15: U.Y.P$A5 30.81,46.37 30.81,46.36 35.98,41.24 | U.X2.P$A5 112.46,17.62 113.95,17.62 114.13,17.56 v114.21,17.14 | v46.86,18.21 46.13,18.22 | v50.01,40.34 50.02,40.35 50.05,40.35 50.05,40.36 50.06,40.36 | 46.13,18.22 45.5,17.59 U.X1.P$A5 | 46.13,18.22 45.93,18.41 v45.93,22.41
  Top 0.17: 35.98,41.24 47.03,41.24 47.88,40.39 49.63,40.39 50.06,40.36
  Top 0.2: U2.45 85.04,36.83 v85.89,37.69
  Bottom 0.15: 49.01,39.06 49.81,39.86 | 49.01,26.59 49.01,39.06 | 49.03,38.69 49.03,39.04 49.02,39.04 49.02,39.05 49.01,39.06 | 105.08,14.91 106.62,13.38 106.62,12.05 107.03,11.64 107.6,11.64 108.08,12.12 108.08,12.16 108.07,12.17 110.22,14.32 114.48,14.32
  Bottom 0.17: v45.93,22.41 49.01,26.59
  Bottom 0.2: 49.81,39.86 v50.01,40.34 | v85.89,37.69 85.08,36.49 85.13,36.47 85.13,36.45 83.14,36.45 79.61,39.99 54.93,39.99 53.66,38.69 49.03,38.69 | v46.86,18.21 47.61,17.46 49.78,17.46 50.78,16.46 93.13,16.46 | v114.21,17.14 114.18,16.81 114.48,16.51 114.48,14.32 | 105.08,14.91 98.43,14.91 96.88,16.46 93.13,16.46 | 93.13,16.46 93.18,16.46
B$I.1  (via drill 0.2)
  Top 0.15: U.Y.P$A6 31.38,46.6 31.38,46.41 | 112.37,18.44 U.X2.P$A6 114.55,18.39 v115.63,17.06 | v49.48,41.06 v49.47,41.05 47.77,41.05 47.76,41.06 | v49.48,41.06 v49.47,41.06 | 50.04,41.09 50.01,41.06 v49.48,41.06
  Top 0.17: 31.38,46.41 36.26,41.66 47.16,41.66 47.76,41.06
  Top 0.2: v52.16,39.51 50.58,41.09 50.04,41.09 | v85.03,37.74 v85.03,37.73 84.63,37.33 U2.46 | U.X1.P$A6 v45.16,22.86 v45.16,22.87
  Bottom 0.15: 47.33,16.89 47.31,16.86 | 49.66,16.89 47.33,16.89 | 47.33,16.89 45.18,19.04 | 104.78,14.46 105.04,14.46 106.31,13.19 106.31,11.91 106.9,11.32 108.14,11.32 110.57,13.9 114.65,13.9 115.63,14.88 115.63,17 v115.63,17.06
  Bottom 0.17: 45.16,22.84 48.56,26.84 | 48.56,39.29 49.28,40.01
  Bottom 0.2: 48.56,26.84 48.56,39.29 | 49.28,40.01 v49.48,41.06 | v85.03,37.74 84.66,37.13 83.22,37.13 79.91,40.46 54.76,40.46 53.78,39.51 v52.16,39.51 | 49.66,16.89 50.48,16.06 96.58,16.06 98.18,14.46 104.78,14.46 | 45.18,19.04 45.17,19.03 45.16,19.04 | 45.35,23.06 v45.17,22.88 45.17,22.84 45.16,22.84 | 45.16,22.84 | 45.16,19.04 45.16,22.84 | 45.16,22.84 45.17,22.85 | 45.16,19.04 45.16,19.01 v45.16,22.87
B$I.2  (via drill 0.2)
  Top 0.15: U.Y.P$B5 30.21,47.77 31.04,47.77 31.04,47.38 36.36,42.06 36.73,42.06 | U.X1.P$B5 44.77,18.01 44.77,21.81 44.53,22.06 44.53,23.46 v44.78,23.71 | 47.01,42.04 46.88,42.06 | U.X2.P$B5 111.97,18 114.2,18 114.86,17.29 114.99,17.15 v115.05,16.27 | v48.83,41.64 v48.83,41.63 47.89,41.63 47.88,41.64 | 48.86,41.66 v48.83,41.64 | v48.83,41.64 v48.83,41.63
  Top 0.17: 47.88,41.64 47.58,42.04 47.01,42.04 | 46.88,42.06 36.73,42.06
  Top 0.2: U2.47 84.12,37.83 v84.12,38.18 84.08,38.21 84.08,38.51 v86.73,41.16 | v52.41,40.4 51.13,41.66 48.86,41.66
  Bottom 0.15: 114.83,17.41 114.83,17.4 114.82,17.39 114.99,17.22 v115.05,16.27
  Bottom 0.17: 48.08,27.36 v44.78,23.71
  Bottom 0.2: 48.08,27.36 48.08,39.51 48.83,40.26 v48.83,41.64 | v84.12,38.18 83.19,38.18 80.42,40.94 80.43,40.95 80.43,40.96 54.53,40.96 53.96,40.39 v52.4,40.39 | v52.4,40.39 52.39,40.39 | v52.4,40.39 v52.41,40.4 | 114.83,17.41 103.73,28.51 103.73,36.06 105.58,37.91 106.03,37.91 106.98,38.86 106.98,40.16 101.63,40.16 97.58,36.11 91.78,36.11 v86.73,41.16
B$I.3  (via drill 0.2)
  Top 0.15: U.Y.P$B6 31.36,48.16 31.36,47.59 36.54,42.41 37.06,42.41 37.07,42.42 37.08,42.41 46.81,42.41 v48.32,42.32 48.38,42.44 | U.X2.P$B6 112.15,19.01 114.81,19.01 v116.43,17.09 | v43.98,24.01 43.98,22.06 44.28,21.76 44.28,18.46 U.X1.P$B6
  Top 0.17: 48.38,42.44 51.76,42.44
  Top 0.2: v52.83,41.36 51.74,42.42 51.76,42.44 | v47.88,16.31 47.88,18.14 46.61,19.41 46.61,22.86 45.16,24.31 44.13,24.31 44.13,24.16 v43.98,24.01 | v78.52,44.54 78.18,44.41 78.18,43.56 78.53,43.21 78.53,42.21 78.43,42.11 78.43,40.31 78.42,40.32 U2.53
  Bottom 0.15: 98.03,13.91 104.43,13.91 105.95,12.39 105.95,11.84 106.82,10.97 108.42,10.97 110.87,13.42 114.83,13.42 116.43,15.02 v116.43,17.09 | v48.32,42.32 48.32,42.36 48.13,42.17 48.13,40.14 | v116.43,17.09
  Bottom 0.17: v43.98,24.01 47.71,27.94
  Bottom 0.2: 48.13,40.14 47.71,39.71 47.71,27.94 | v52.83,41.36 52.85,41.36 52.85,41.35 53.1,41.5 78.42,41.5 79.53,42.61 79.53,43.86 78.83,44.56 v78.52,44.54 | v47.88,16.31 49.53,16.31 50.18,15.66 96.28,15.66 98.03,13.91
B$I.4  (via drill 0.2)
  Top 0.15: U.Y.P$C5 30.22,48.56 31.56,48.56 31.68,48.44 31.68,47.71 36.52,42.87 37.26,42.87 37.26,42.88 37.26,42.89 | U.X1.P$C5 43.97,18.04 43.97,21.46 43.38,21.94 43.38,24.46 43.62,24.69 | 46.53,42.91 46.53,42.89 | U.X2.P$C5 111.12,17.99 111.12,19.07 111.12,19.06 111.12,19.07 111.44,19.39 115.22,19.39 v117.21,17.06 | 46.98,23.21 45.31,24.89 | v43.81,24.89 v43.8,24.88 43.8,24.86 43.83,24.86
  Top 0.17: 46.53,42.89 37.26,42.89 | v47.59,42.91 46.53,42.91
  Top 0.2: U2.54 77.92,42.88 v77.98,42.91 | v48.48,15.69 48.48,18.06 46.98,19.56 46.98,23.21 | 43.62,24.69 43.83,24.86 45.28,24.86 45.31,24.89
  Bottom 0.15: 47.56,42.86 47.56,42.89 | 47.56,42.86 | v47.59,42.91 47.53,42.86 47.56,42.86 | v117.21,17.06 117.21,15.17 114.85,12.81 111.18,12.81 109.17,10.63 106.51,10.63 105.61,11.61 105.6,11.61
  Bottom 0.17: v43.81,24.89 47.33,28.46 | 47.56,40.14 47.56,42.86
  Bottom 0.2: 47.33,28.46 47.33,39.91 47.56,40.14 | v77.98,42.91 77.83,42.79 76.88,42.79 76.38,43.29 47.98,43.29 47.56,42.86 | v48.48,15.69 48.56,15.76 49.38,15.76 49.88,15.26 95.78,15.26 97.73,13.31 103.9,13.31 105.6,11.61
B$I.5  (via drill 0.2)
  Top 0.15: U.Y.P$C6 31.68,48.96 31.99,48.65 31.99,47.86 36.43,43.42 37.22,43.42 | U.X1.P$C6 43.56,18.56 43.56,21.19 42.88,21.86 v42.88,25.06 | 46.83,43.41 37.21,43.41 37.22,43.42 | 46.83,43.41 46.86,43.39 | 47.08,43.66 46.83,43.41 | U.X2.P$C6 110.73,19.11 111.39,19.77 115.74,19.77 117.98,17.54 v117.98,17.09 | 37.22,43.42 37.26,43.42
  Top 0.2: U2.55 77.35,43.28 v77.51,43.59 | v49.18,15.04 49.18,17.91 47.33,19.76 47.33,23.61 45.43,25.51 43.33,25.51 v42.88,25.06 | v47.48,43.66 47.08,43.66
  Bottom 0.15: 46.86,29.09 46.86,43.39 46.88,43.41 47.13,43.66 | 105.58,10.96 106.32,10.22 110.06,10.22 112.16,12.32 114.98,12.32 118,15.34 118,17.07 v117.98,17.09
  Bottom 0.17: v42.88,25.06 46.86,29.09
  Bottom 0.2: v77.51,43.59 77.13,43.76 47.43,43.76 | 46.88,43.41 46.96,43.49 | v49.18,15.04 49.41,14.86 95.28,14.86 97.38,12.76 103.78,12.76 105.58,10.96 | v117.98,17.09 118.03,17.06 | 47.13,43.66 v47.48,43.66
  Bottom 0.27: 47.43,43.76 47.43,43.66 v47.48,43.66
B$I.6  (via drill 0.2)
  Top 0.15: U.Y.P$D5 30.22,49.36 31.76,49.36 32.34,48.78 32.34,47.98 36.31,44.01 37.11,44.01 | U.X1.P$D5 43.15,17.98 43.15,20.98 42.28,21.81 42.28,25.31 v42.93,25.96 | U.X2.P$D5 110.33,17.97 110.33,19.16 111.44,20.29 116.2,20.26 118.74,17.72 118.74,17.07 v118.74,16.73
  Top 0.17: v46.38,44.01 37.11,44.01
  Top 0.2: U2.1 70.91,38.34 70.93,38.36 v70.93,44.41 | v49.83,14.26 49.83,17.86 47.71,19.99 47.71,23.99 45.63,26.06 43.03,26.06 v42.93,25.96
  Bottom 0.15: 46.38,44.04 46.39,44.03 v46.39,44.02 v46.38,44.01 | 103.33,12.11 105.56,9.72 110.53,9.72 112.8,11.99 116.37,11.99 118.75,14.37 v118.75,16.73 v118.74,16.73
  Bottom 0.17: v42.93,25.96 46.38,29.41
  Bottom 0.2: 46.38,29.41 v46.38,44.01 46.63,44.26 70.68,44.26 v70.93,44.41 | v49.83,14.26 50.33,14.46 94.73,14.46 97.08,12.11 103.33,12.11
B$I.7  (via drill 0.2)
  Top 0.15: U.Y.P$D6 31.81,49.76 32.67,48.9 32.67,48.09 36.27,44.49 37.08,44.49 37.08,44.51 37.09,44.51 | U.X1.P$D6 42.76,20.84 41.28,22.31 41.28,25.24 v41.93,25.89 | U.X2.P$D6 109.98,18.44 109.98,19.26 111.48,20.76 116.35,20.74 119.48,17.61 v119.48,17.06 | U.X1.P$D6 | U.X1.P$D6 | U.X1.P$D6 | U.X1.P$D6
  Top 0.17: 48.11,20.24 48.11,23.81
  Top 0.2: U2.2 63.44,37.83 60.46,40.81 v60.46,44.87 | v58.26,47.04 57.78,47.54 54.31,47.54 51.53,44.76 v46.05,44.75 45.96,44.75 45.93,44.66 45.78,44.51 37.09,44.51 | v50.56,13.69 50.56,17.76 48.11,20.24 | 48.11,23.81 48.11,24.29 45.78,26.61 42.63,26.61 41.93,25.91 v41.93,25.89 41.93,25.86
  Bottom 0.15: 104.78,9.61 104.95,9.28 110.84,9.28 113.17,11.61 116.8,11.61 119.48,14.29 119.47,14.3 v119.47,17.05 v119.48,17.06
  Bottom 0.17: v41.93,25.89 45.61,29.56
  Bottom 0.2: v60.46,44.87 59.21,46.06 v58.26,47.04 | v50.56,13.69 51.16,14.09 94.16,14.09 96.73,11.51 102.88,11.51 104.78,9.61 | v46.05,44.75 45.91,44.76 45.93,44.66 45.61,44.34 45.61,29.56
B$I.8  (via drill 0.2)
  Top 0.15: U.Y.P$J5 30.25,54.17 31.71,54.17 32.02,54.47 33.99,54.47 37.92,50.54 40.12,50.54 40.12,50.57 v40.11,50.59 | U.X1.P$J5 38.36,17.99 38.36,20.14 37.68,20.81 37.68,31.86 v38.11,32.29 | U.X2.P$J5 105.53,17.99 105.53,20.33 95.54,30.32 | v62.75,37.71 62.74,37.72 | v62.76,37.71 v62.75,37.71 | U2.3 63.14,37.33 v62.75,37.71 | v60.33,33.54 v60.33,33.53 | v60.33,33.53 60.33,33.51 60.31,33.54 v57.31,33.54 | v39.8,34.29 39.78,34.27 | v39.8,34.29 39.91,34.29 | 40.05,34.4 39.91,34.4 v39.8,34.29 | 60.41,33.54 v60.34,33.54 v60.33,33.53
  Top 0.17: 40.05,34.4 40.96,34.4 41.22,33.88 50.33,33.88
  Top 0.2: v58.21,37.71 58.31,37.61 58.3,37.6 60.41,35.5 60.41,33.54 | 90.51,30.31 90.48,30.31 | 90.51,30.31 v90.53,30.34 | 95.54,30.32 95.53,30.31 90.51,30.31 | 50.33,33.88 50.49,33.88 51.07,33.3 53.1,33.3 53.64,33.84 53.63,33.85 v53.68,33.78
  Bottom 0.15: 39.91,50.39 v40.11,50.59 | 60.4,33.54 | 60.41,33.54 60.4,33.54 | 60.4,33.54 60.36,33.5 | 39.91,34.29 39.9,34.29 39.88,34.27 39.87,34.29 v39.8,34.29
  Bottom 0.17: v38.11,32.29 39.91,34.29 39.91,50.39 | 60.41,33.54 60.4,33.54 v60.33,33.54 60.33,33.01 60.89,32.45 62.14,32.45 62.14,32.48
  Bottom 0.2: v53.68,33.78 54.18,33.54 v57.31,33.54 | v58.21,37.71 v62.76,37.71 | v90.53,30.34 64.29,30.34 62.14,32.48
B$I.9  (via drill 0.2)
  Top 0.15: U.Y.P$J6 30.79,53.86 32.25,53.86 32.4,54.01 33.78,54.01 37.88,49.91 v40.55,49.91 | 67.8,36.57 61.6,36.57 | 61.6,36.57 61.56,36.49 61.68,36.49 | 61.6,36.57 v61.61,34.34 | U.X2.P$J6 105.93,20.53 95.43,31.03 | 94.49,31.03 94.51,31.01 | v38.98,32.41 38.13,31.56 38.13,31.39 38.13,21.01 38.76,20.39 U.X1.P$J6 | v61.21,32.99 61.08,32.86 60.88,32.74 v58.12,32.74 | v40.43,33.74 v40.44,33.74 40.45,33.72 | U.X1.P$J6 | U.X1.P$J6
  Top 0.17: v84.4,31.01 v84.4,31 | 70.9,36.35 70.86,36.35 | 70.9,36.35 U2.5 | v72.69,36.7 72.34,36.35 70.9,36.35 | 40.45,33.72 v40.43,33.74 | 40.45,33.72 40.49,33.72 | 40.45,33.72 40.71,33.46 49.5,33.46 49.67,33.53 50.32,33.53 50.89,32.95 52.6,32.95 52.89,32.67 54.42,32.67 54.42,32.77 v54.59,32.81
  Top 0.2: U2.5 67.99,36.33 67.8,36.57 | 94.51,31.01 v84.4,31.01 | 95.43,31.03 94.49,31.03
  Bottom 0.15: v40.43,33.74 40.41,33.74 40.41,33.72 40.42,33.7 39.13,32.41 v38.98,32.41 | v54.59,32.81 57.97,32.81 v58.12,32.74 | v61.61,34.34 v61.6,34.34 61.6,33.38 v61.21,32.99
  Bottom 0.17: v40.43,33.74 40.43,49.36 v40.55,49.91 | 79.07,35.25 78.14,35.27
  Bottom 0.2: v84.4,31 83.31,31 79.07,35.25 | 78.14,35.27 73.27,35.27 72.69,35.85 v72.69,36.7
B$I.10  (via drill 0.2)
  Top 0.15: U.X1.P$K5 37.56,17.99 37.56,19.96 37.03,20.49 37.03,34.04 37.16,34.16 v37.63,34.61 | 38.95,35.89 v38.76,35.76 | U.X2.P$K5 104.73,17.99 104.73,19.92 98.69,25.96 97.63,25.96 97.66,25.99 | v59.37,34.99 59.37,34.96 58.85,34.44 v56.69,34.44 | v73.25,33.79 v73.24,33.78 72.71,34.31 72.5,34.31 72.49,34.33 U2.9 | U.Y.P$K5 30.21,54.95 31.38,54.95 31.75,55.32 33.63,55.32 33.66,55.35 34.23,55.36 37.32,52.27 38.82,52.27 v38.83,52.29
  Top 0.17: 38.95,35.89 40.88,35.89 41.84,34.91 50.59,34.91 50.83,34.61 52.78,34.61 v52.98,34.44 | 93.93,29.71 82.33,29.71 78.22,33.82 76.59,33.82 v76.55,33.78 | v73.25,33.79
  Top 0.2: U2.9 70.05,34.33 69.6,33.94 v64.9,33.94 | 97.66,25.99 93.93,29.71
  Bottom 0.15: v64.9,33.94 65.06,33.98 65.08,33.95 64.85,34.06 | v38.76,35.76 38.83,35.76 38.83,35.71 v37.63,34.61 | v38.84,52.28 38.85,52.28 | v38.84,52.28 v38.83,52.29 | 38.76,52.21 v38.83,52.28 v38.84,52.28 | 56.08,34.44 v56.69,34.44
  Bottom 0.17: v38.76,35.76 38.76,52.21
  Bottom 0.2: 56.08,34.44 v52.98,34.44 | v76.55,33.78 v73.25,33.79 | 64.85,34.06 64.02,34.93 | 64.02,34.93 63.97,34.99 63.92,34.99 | 63.92,34.99 v59.37,34.99 | 64.02,34.93 63.92,34.99
B$I.11  (via drill 0.2)
  Top 0.15: U.Y.P$K6 30.65,54.59 31.6,54.59 31.98,54.97 34.13,54.97 37.83,51.27 39.39,51.27 39.39,51.28 v39.38,51.29 | U.X1.P$K6 37.91,18.44 37.91,20.11 37.38,20.64 37.38,33.37 v37.78,33.77 | U.X2.P$K6 105.13,20.03 98.58,26.58 97.72,26.58 | v39.25,35.05 40.51,35.05 40.78,35.32
  Top 0.17: 40.78,35.32 41.69,34.4 49.95,34.4
  Top 0.2: 97.72,26.58 98,26.58 v97.88,26.61 | 49.95,34.4 50.13,34.4 50.3,34.24 50.99,34.24 v51.31,33.91 | U2.29 78.92,26.57 v79.27,26.32
  Bottom 0.15: 59.41,26.56 52.3,33.65 | 39.41,51.29 39.42,51.27 39.42,51.26 39.41,51.26 v39.38,51.29 | 90.5,26.26 90.53,26.29 | 90.48,26.26 90.5,26.26 | 90.5,26.26 90.45,26.21 79.29,26.21 | v39.25,35.05 39.41,35.21 39.41,35.31 39.41,35.19 39.21,34.99 39.03,34.99 39.03,35.02 | 39.03,35.02 39.07,35.06 | 39.03,35.02 v37.78,33.77
  Bottom 0.17: 39.41,35.31 39.41,51.29
  Bottom 0.2: 59.41,26.56 78.18,26.56 78.98,26.56 | v97.88,26.61 90.83,26.61 90.48,26.26 | 52.3,33.65 52.3,33.64 | 52.3,33.65 | v51.31,33.91 52.03,33.91 52.3,33.65 | 79.29,26.21 79.29,26.23 78.98,26.53 78.98,26.56 | 78.98,26.56 78.97,26.55 79.35,26.17 v79.27,26.32
B$I.12  (via drill 0.2)
  Top 0.15: U.Y.P$L5 30.21,55.76 31.19,55.76 31.42,55.99 34.6,55.99 35.43,55.16 35.43,55.06 36.71,53.78 37.61,53.78 37.59,53.76 v37.53,53.76 | U.X1.P$L5 36.75,17.99 36.75,19.65 36.15,20.26 36.16,35.81 v36.41,35.81 | v58.68,36.04 v54.18,36.04 | U.X2.P$L5 103.93,17.99 103.93,18.91 103.93,19.61 98.26,25.29 97.09,25.29 96.89,25.49 93.56,28.81 | 82.2,28.81 79.55,31.46 | U2.11 70.97,33.29 v72.43,33.29
  Top 0.17: v37.56,37.21 40.81,37.21 42.2,35.81 v51.13,35.75
  Top 0.2: U2.11 63.22,33.32 v62.4,36.02 | 93.56,28.81 82.2,28.81 | 79.55,31.46 77.92,31.46 77.91,32.66 v77.31,33.08
  Bottom 0.15: v36.41,35.81 v37.56,37.21 37.56,53.76 v37.53,53.76 | v72.43,33.29 72.46,33.08 v77.31,33.08 | v58.68,36.04 58.7,36.04 58.71,36.05 58.67,36 62.29,36 62.39,36.1 62.4,36.09 v62.4,36.02 | 51.63,36.04 | v54.18,36.04
  Bottom 0.2: 51.63,36.04 v51.13,35.75 | v54.18,36.04 51.63,36.04
B$I.13  (via drill 0.2)
  Top 0.15: U.Y.P$L6 31.27,55.36 31.58,55.67 33.92,55.67 | U.X1.P$L6 37.13,18.42 37.13,19.71 36.61,20.24 36.61,34.66 | 36.61,34.66 36.58,34.64 | 40.87,36.52 38.5,36.52 v38.16,36.56 | 36.61,34.66 36.86,34.91 v36.88,34.91 | v38.13,53.11 38.08,53.16 38.07,53.15 36.87,53.15 34.73,55.29 34.7,55.4 34.43,55.67 33.92,55.67 | U.X2.P$L6 104.33,19.79 98.49,25.63 97.32,25.63 93.7,29.26 93.69,29.26 | v54.78,35.34 54.78,35.19 57.85,32.19 62.02,32.18 62.17,32.33 U2.13 | U2.13 70.93,32.35 70.94,32.34 71.52,32.34 | U2.13 | 33.92,55.67 33.89,55.67
  Top 0.17: 42.05,35.34 40.87,36.52 | 79.23,32.31 79.23,32.28 82.23,29.29 82.3,29.26 | 42.05,35.34 42.03,35.35 | 42.05,35.34 50.71,35.34 50.87,35.17 51.72,35.17 51.83,35.36 v51.86,35.34
  Top 0.2: 93.69,29.26 82.3,29.26 | 79.23,32.31 v78.61,32.31 | v73.14,32.34 71.52,32.34
  Bottom 0.15: 38.16,41.11 38.13,41.14 v38.13,53.11 | v38.16,36.56 38.13,36.54 38.13,36.16 v36.88,34.91
  Bottom 0.17: v38.16,36.56 38.16,41.11
  Bottom 0.2: v54.78,35.34 v51.86,35.34 | v78.61,32.31 78.52,32.34 v73.14,32.34
B$I.14  (via drill 0.2)
  Top 0.15: U.Y.P$M5 30.22,56.56 31.12,56.56 31.22,56.66 34.24,56.66 34.27,56.63 34.84,56.63 35.1,56.39 36.17,56.39 v36.25,56.31 | U.X1.P$M5 35.96,17.99 35.96,19.35 35.28,20.03 35.28,37.71 v35.41,37.71 v35.42,37.7 | 40.88,38.68 v36.29,38.68 | U.X2.P$M5 103.13,17.98 103.13,19.36 97.9,24.6 96.66,24.6 96.48,24.79 96.48,24.82 93.56,27.76 | 52.33,36.8 52.53,36.84 57.34,32.02 v57.44,31.83
  Top 0.17: 42.72,36.84 40.88,38.68
  Top 0.2: v57.44,31.83 U2.14 | 52.33,36.8 42.72,36.84 | 93.56,27.76 v82.78,27.76 | v63.71,29.89 v58.98,29.89 | v36.25,56.32 v36.25,56.31 36.27,56.29
  Bottom 0.15: v57.44,31.83 57.39,31.83 57.41,31.85 58.98,30.28 v58.98,29.89 | 36.26,38.63 36.27,38.64 | 36.23,38.63 36.26,38.63 | v35.42,37.7 35.42,37.79 36.26,38.63 | 36.26,38.67 v36.28,38.67 | 36.26,38.66 36.26,38.67 | v36.25,56.31 36.25,38.67 36.26,38.67
  Bottom 0.2: v82.78,27.76 80.66,29.89 v63.71,29.89 | 36.23,38.63 36.23,38.66 36.26,38.66 v36.28,38.68 v36.29,38.68 | v36.25,56.32 v36.24,56.32 36.23,56.31 v36.25,56.31
B$I.15  (via drill 0.2)
  Top 0.15: 36.36,19.48 35.73,20.1 35.73,36.81 35.88,36.96 v35.88,37.01 | 93.29,28.4 93.45,28.39 96.72,25.16 96.72,25.13 96.89,24.95 98.09,24.95 103.53,19.52 U.X2.P$M6 | 82.12,28.4 79.76,30.77 | 40.9,38.01 40.9,38 40.88,37.98 42.55,36.31 52.08,36.31 | U.Y.P$M6 31.16,56.16 31.31,56.31 34.11,56.31 34.11,56.33 34.69,56.33 34.94,56.08 35.64,56.08 35.94,55.78 35.94,55.42 36.87,54.49 v36.88,54.5 v36.88,54.51
  Top 0.17: 40.9,38.01 37.37,38.01
  Top 0.2: 52.08,36.31 57.17,31.23 U2.15 72.52,31.33 v72.76,31.56 | v77.25,31.72 77.99,30.77 79.76,30.77 | 93.29,28.4 82.12,28.4 | U.X1.P$M6 36.38,18.41 36.36,18.44 36.36,19.48 | v36.88,37.96 v36.87,37.97 36.91,38.01 37.37,38.01
  Bottom 0.15: v35.88,37.01 36.83,37.96 36.85,37.94 36.86,37.94 v36.88,37.96
  Bottom 0.17: v36.88,37.96 v36.88,54.51
  Bottom 0.2: v72.76,31.56 77.01,31.56 v77.25,31.72
B$I.16  (via drill 0.2)
  Top 0.15: U.Y.P$E5 30.22,50.16 31.91,50.16 31.91,50.14 32.98,49.06 32.98,48.21 33,48.21 36.13,45.08 36.95,45.08 | U.X1.P$E5 42.36,17.99 42.36,20.74 40.93,22.16 40.93,25.99 41.91,26.96 | U.X2.P$E5 109.53,17.99 109.53,19.3 111.48,21.25 116.41,21.21 120.26,17.36 v120.27,17.04 | 41.91,26.96 40.98,26.01 | v41.86,26.9 41.9,26.95 | v41.86,26.9 41.91,26.96 | 42.03,27.06 42.01,27.06 v41.86,26.9
  Top 0.17: v45.15,45.08 36.95,45.08 | v44.98,30.01 45.8,30.83
  Top 0.2: 45.8,30.83 U2.16 | v51.16,13.05 51.28,13.36 51.28,17.56 48.48,20.36 48.48,24.66 46.08,27.06 42.03,27.06
  Bottom 0.15: 41.9,26.96 41.91,26.96 | v41.86,26.9 41.9,26.96 | 41.9,26.96 41.83,26.89 | 102.38,10.91 104.47,8.82 111,8.82 113.31,11.14 117.41,11.14 120.32,14.04 120.27,14.09 120.27,17.01 120.28,17.01
  Bottom 0.17: 41.91,26.96 45.08,30.14 v44.98,30.01
  Bottom 0.2: v44.98,30.01 v45.15,45.08 | v51.16,13.05 51.68,13.66 93.48,13.66 96.23,10.91 102.38,10.91 | 120.28,17.01 120.27,17.03 v120.27,17.04
B$I.17  (via drill 0.2)
  Top 0.15: U.Y.P$E6 31.95,50.56 33.34,49.17 33.34,48.33 36.18,45.52 37.09,45.52 | U.X1.P$E6 41.98,18.41 41.98,20.64 40.59,22.05 40.59,26.62 v40.83,26.96 40.76,26.76 | U.X2.P$E6 109.13,19.51 111.28,21.66 116.63,21.66 121.03,17.26 v121.03,17.07 | 60.95,35.96 57.71,39.2 57.72,39.21 v57.72,44.82 v57.71,44.84 | 37.09,45.52 37.14,45.52 | 37.08,45.51 37.09,45.52
  Top 0.17: 37.08,45.51 44.61,45.51 44.81,45.71 v45.68,45.67 45.78,45.41 v47.43,45.41
  Top 0.2: U2.12 61.97,32.84 61.97,33.15 60.95,34.16 60.95,35.96 | v51.86,12.39 51.86,17.74 48.93,20.66 48.93,24.96 46.38,27.51 41.38,27.51 v40.83,26.96 41.03,27.16
  Bottom 0.15: 103.88,8.36 104.03,8.21 111.75,8.21 114.02,10.48 117.69,10.48 121.07,13.85 121.07,17.03 v121.03,17.07
  Bottom 0.17: v40.83,26.96 44.56,30.59 44.56,45.49 44.83,45.71 | v57.71,44.84 57.13,45.41 v47.43,45.41 | 44.83,45.71 v45.68,45.67 | 44.61,45.51 44.58,45.51 44.78,45.71 44.83,45.71
  Bottom 0.2: v51.86,12.39 51.88,12.36 52.8,13.28 92.91,13.28 95.97,10.21 102.03,10.21 103.88,8.36
B$I.18  (via drill 0.2)
  Top 0.15: U.Y.P$F5 30.22,50.96 31.86,50.96 32.13,50.97 33.64,49.45 33.64,48.54 35.95,46.23 36.87,46.23 36.87,46.22 36.88,46.21 | U.X1.P$F5 41.56,17.99 41.56,20.61 40.23,21.94 40.23,27.21 40.29,27.27 | U.X2.P$F5 108.73,17.99 108.73,19.66 111.08,22.01 116.83,22.01 121.87,17.02 v121.88,16.45 | 40.28,27.29 40.31,27.29 40.29,27.27 | U2.8 v68.45,34.83 v68.44,34.82 | 40.98,27.88 41.06,27.96 41.08,27.96 | 40.98,27.88 v40.95,27.88 40.93,27.91 40.29,27.27 | 40.98,27.88 40.96,27.86 | v58.51,44.84 58.48,44.81
  Top 0.17: 36.88,46.21 v44.21,46.21 46.76,46.21 46.96,46.41 v46.98,46.46
  Top 0.2: 58.48,44.81 58.48,39.51 v60.88,37.11 | v52.73,11.76 52.73,17.51 49.41,20.86 49.41,25.19 46.63,27.96 41.08,27.96
  Bottom 0.15: v40.95,27.88 44.21,31.19 | 67.38,34.86 67.37,34.85 67.4,34.82 v68.44,34.82 | v121.88,16.45 121.86,16.43 | v58.51,44.84 v58.5,44.83 58.5,44.82 | 103.63,7.71 103.92,7.43 111.87,7.43 114.46,10.01 118.51,10.01 121.79,13.29 121.86,13.36 121.86,16.43 | 121.86,16.43 | 121.86,16.43 121.77,16.34
  Bottom 0.17: 44.21,31.19 v44.21,46.21 | v46.98,46.46 47.48,46.46 47.91,46.04 57.52,45.99 58.51,45 v58.51,44.84
  Bottom 0.2: 67.38,34.86 65.66,36.59 61.41,36.59 v60.88,37.11 | v52.73,11.76 52.73,12.61 52.98,12.86 92.33,12.86 95.58,9.61 101.73,9.61 103.63,7.71
B$I.19  (via drill 0.2)
  Top 0.15: 30.65,51.36 31.78,51.36 32.18,51.37 33.98,49.56 33.98,48.65 35.74,46.89 36.66,46.89 | U.X1.P$F6 41.18,18.41 41.18,20.54 39.93,21.79 39.93,27.88 40.09,28.04 | v43.56,46.89 44.42,46.89 44.77,46.54 45.58,46.54 46.06,47.01 46.08,47.04 | U.X2.P$F6 108.33,19.76 110.88,22.31 117.31,22.31 122.52,17.09 122.63,17.07 122.59,17.07 v122.59,17.06 v122.58,17.05 | 30.65,51.36 30.65,51.35 | 30.65,51.36 U.Y.P$F6 | 30.65,51.36 U.Y.P$F6 | 30.65,51.36 | 40.53,28.46 40.51,28.46 40.09,28.04 | 40.09,28.04 v40.14,28.07 | 36.66,46.89 36.67,46.89 | 36.66,46.89 | 59.56,39.85 59.56,39.87 59.54,39.88 59.55,39.89 v59.55,44.88
  Top 0.17: v43.56,46.89 36.66,46.89 | 46.06,47.01 v47.86,47.01
  Top 0.2: U2.4 68.17,36.83 68.11,36.94 62.58,36.94 59.56,39.85 | v53.56,11.75 53.56,17.31 49.93,20.91 49.93,25.46 46.93,28.46 40.53,28.46
  Bottom 0.15: 58.64,45.68 58.63,45.67 58.76,45.67 v59.55,44.88 | 103.13,7.11 103.65,6.59 112.21,6.59 115.16,9.54 119.05,9.54 122.63,13.13 122.63,17.04 122.59,17.04 v122.58,17.05
  Bottom 0.17: v40.14,28.07 43.56,31.49 v43.56,46.89 | v47.86,47.01 48.48,46.39 57.94,46.39 58.64,45.68
  Bottom 0.2: v53.56,11.75 54.23,12.46 91.73,12.41 95.23,8.91 101.33,8.91 103.13,7.11 | v122.58,17.05 122.63,17.07
B$I.20  (via drill 0.2)
  Top 0.15: U.Y.P$G5 30.25,51.76 32.28,51.76 34.36,49.68 34.36,48.85 35.67,47.54 36.48,47.54 | U.X1.P$G5 40.76,17.99 40.76,20.46 39.58,21.64 39.58,28.61 v39.93,28.96 | 82.92,38.34 U2.48 | U.X2.P$G5 107.93,17.99 107.93,20.89 107.94,20.9 107.93,20.91
  Top 0.17: v43.01,47.54 36.48,47.54
  Top 0.2: 107.93,20.91 107.93,21.32 95.33,33.96 94.58,33.96 94.59,42.06 86.13,42.06 86.14,42.09 83.58,39.52 v83.58,39.52 v83.57,39.53 | 82.92,38.34 83.05,38.34 83.49,38.78 83.49,39.44 v83.57,39.52 v83.57,39.53 | v83.57,39.53 v83.58,39.53
  Bottom 0.15: 43.02,47.52 43.04,47.52 | v43.01,47.53 43.02,47.52 | v43.01,47.53 v43.01,47.54 | 43.02,47.52 42.95,47.52 42.91,47.56 42.94,47.53 v43.01,47.53 | 43.01,47.13 43.01,47.14 v43.01,47.53
  Bottom 0.17: v39.93,28.96 43.01,32.04 43.01,47.13
  Bottom 0.2: 42.91,47.56 43.11,47.76 49.78,47.76 49.93,47.61 68.26,47.61 68.31,47.56 68.18,47.54 69.47,47.54 72.09,44.92 76.89,44.91 76.89,44.92 77.13,45.16 78.93,45.16 83.58,40.51 83.57,40.5 v83.57,39.53
B$I.21  (via drill 0.2)
  Top 0.15: U.Y.P$G6 30.65,52.19 32.36,52.19 34.7,49.84 34.7,49 35.57,48.13 36.41,48.13 | U.X1.P$G6 40.33,18.42 40.33,20.44 39.26,21.51 39.26,29.24 v40.01,29.94 | 107.53,20.91 U.X2.P$G6 | 36.41,48.13 36.43,48.13 | 36.41,48.14 36.41,48.13 | v86.47,37.06 v86.47,37.05 v86.47,37.04 85.76,36.33 U2.44 | v42.42,48.11 v42.42,48.12 | 42.41,48.14 42.39,48.12 v42.41,48.12 | v42.42,48.11 42.43,48.11 | v42.41,48.11 v42.42,48.11 | 42.41,48.14 v42.41,48.12 | v42.41,48.12 42.41,48.13 | v42.42,48.11 v42.41,48.12 | v42.41,48.11 v42.41,48.12 42.41,48.13 | 42.41,48.14 42.41,48.13 | v42.41,48.11 v42.41,48.12 | v42.41,48.11 v42.42,48.1
  Top 0.17: 42.46,48.14 42.41,48.14 36.41,48.14
  Top 0.2: v86.47,37.05 86.47,40.1 87.63,41.26 87.63,41.23 | 107.53,20.91 94.98,33.46 93.98,33.46 93.73,33.71 93.73,38.07 93.1,38.7 91.88,38.7 91.08,39.5 91.08,40.92 90.72,41.28 87.68,41.28 87.63,41.23 | 87.63,41.23 87.62,41.22 | 42.41,48.14 v42.42,48.12 v42.41,48.11 42.37,48.11 42.36,48.12 42.37,48.13 42.41,48.13
  Bottom 0.15: 86.58,37.26 86.58,37.16 v86.47,37.05 | 42.46,48.14 42.45,48.13 42.42,48.13 | 42.42,48.13 42.41,48.13 | 42.41,48.14 v42.42,48.12 42.42,48.13 | v42.41,48.12 v42.41,48.11 | 42.42,48.13 v42.41,48.12 | 42.41,48.14 42.41,48.13 | 42.41,48.13 v42.41,48.12 | 42.41,48.14 v42.41,48.12 | 42.38,48.09 42.38,48.11 42.41,48.14 | v42.41,48.12 42.38,48.09 | 42.38,48.09 42.38,48.07 | v42.41,48.12 v42.42,48.11 | 42.41,48.14 42.41,48.13 v42.41,48.12
  Bottom 0.17: v40.01,29.94 42.43,32.41 42.42,47.87
  Bottom 0.2: 86.58,37.26 86.58,38.06 79.15,45.48 78.92,45.71 77.08,45.71 76.83,45.46 72.53,45.46 72.51,45.48 72.49,45.48 69.82,48.16 68.91,48.16 68.93,48.14 42.46,48.14 42.41,48.14 | v42.41,48.12 v42.42,48.12 v42.41,48.11 | v42.41,48.11 | v42.41,48.11 v42.42,48.11 | v42.42,48.11 42.42,47.87 | v42.42,48.11 42.43,48.12
B$I.22  (via drill 0.2)
  Top 0.15: U.Y.P$H6 30.72,52.85 32.78,52.85 35.47,50.16 35.47,49.29 35.49,49.27 36.34,49.27 36.36,49.29 | 39.56,19.19 U.X1.P$H6 | 39.56,19.19 39.58,19.21 | 39.56,19.19 39.56,20.68 38.91,21.34 38.91,29.89 38.99,29.89 v40.08,30.98 | U.X2.P$H6 106.76,18.42 106.76,20.68 106.97,20.89 | v85.51,34.08 85.51,34.07 | v85.51,34.08 v85.51,34.09 | 85.51,34.33 85.51,34.32 v85.51,34.08 | 85.53,34.05 85.51,34.05 v85.51,34.08 | 85.53,34.06 85.53,34.05 | 85.53,34.05 85.54,34.05
  Top 0.2: 85.51,34.33 U2.40 | 85.53,34.06 85.53,32.39 85.69,32.17 94.64,32.17 94.65,32.16 95.67,32.19 106.97,20.89 | 36.36,49.29 40.76,49.29 40.93,49.46 41.63,49.46 v41.83,49.26
  Bottom 0.15: v40.08,30.98 40.08,31.07 41.86,32.85 41.86,32.86 41.87,49.02 41.87,49.22 v41.83,49.26 | 42.43,48.74 42.43,48.73
  Bottom 0.2: v85.51,34.09 87.41,35.99 87.41,38.36 80.08,45.64 79.56,46.16 76.73,46.16 76.43,45.86 72.93,45.86 70.06,48.73 69.09,48.73 69.08,48.74 42.43,48.74 | 41.87,49.02 42.15,48.73 42.43,48.73
B$I.23  (via drill 0.2)
  Top 0.15: U.Y.P$H5 30.21,52.55 32.52,52.55 35.06,50.01 35.06,49.19 35.5,48.75 36.23,48.75 36.24,48.75 | U.X1.P$H5 39.16,17.99 39.16,20.54 38.48,21.21 38.48,30.31 v38.86,30.74 | U.X2.P$H5 106.33,17.97 106.33,20.85
  Top 0.17: v41.03,48.74 36.24,48.75
  Top 0.2: U2.36 83.32,32.33 v84.43,33.44 84.03,33 84.86,32.16 85.43,31.59 94.46,31.59 94.39,31.58 95.64,31.58 106.33,20.85
  Bottom 0.15: 41.01,32.85 40.98,48.51 41.03,48.79 | 41.03,48.79 41.04,48.78 v41.04,48.75 v41.03,48.74 | 41.05,48.77 41.05,48.76 | 41.05,48.77 41.03,48.79 | 41.06,48.86 41.05,48.86 41.05,48.77
  Bottom 0.17: 41.01,32.85 v38.86,30.74
  Bottom 0.2: 41.06,48.86 41.06,49.46 41.51,49.91 41.51,49.89 42.57,49.89 43.17,49.29 70.43,49.29 72.22,47.57 82.26,47.56 82.26,44.19 87.86,38.59 87.86,35.39 86.1,33.63 86.1,33.61 86.09,33.61 85.65,33.17 84.7,33.17 v84.43,33.44
B$I.24  (via drill 0.2)
  Top 0.15: U.Y.P$N5 30.22,57.36 30.93,57.37 31.18,57.62 v34.67,57.62 | U.X1.P$N5 35.17,17.98 35.17,19.25 34.36,20.06 34.36,37.84 34.28,37.91 34.28,38.91 34.31,38.96 34.31,39.11 34.36,39.16 34.56,39.24 | U.X2.P$N5 102.33,17.99 102.33,18.84 97.22,23.95 95.54,23.95 95.54,23.99 95.32,24.21 | 34.56,39.24 34.53,39.24 34.52,39.23 34.49,39.26 34.43,39.26 | 34.56,39.24 v34.5,39.19 | 80.46,27.08 80.43,27.08 | 80.43,27.08 v80.43,27.01 | 80.46,27.09 80.46,27.08 | 80.46,27.08 | 80.43,27.07 80.42,27.07 80.42,27.12 | 80.43,27.08 80.43,27.07 | 80.43,27.07 80.44,27.07
  Top 0.17: v49.86,37.39 43.03,37.39 41.16,39.26 34.43,39.26
  Top 0.2: 80.42,27.12 U2.32 | 95.32,24.21 92.45,27.09 80.46,27.09 | v34.67,57.61 v34.67,57.62 | v34.68,57.61 v34.67,57.61 | v34.67,57.61 34.66,57.6
  Bottom 0.15: 34.73,45.86 34.68,45.91 34.67,45.9 34.65,45.9 34.68,50.97 34.67,51.02 35.54,51.87 35.54,54.68 34.67,55.55 v34.67,57.62 | v80.43,27.01 59.48,27.01 51.8,34.74 50.98,34.74 49.88,35.98 | 34.7,57.6 v34.69,57.6 v34.68,57.61 v34.67,57.62 | v34.67,57.62 34.61,57.62
  Bottom 0.17: 34.73,39.51 34.73,45.86 | 49.88,37.41 v49.86,37.39 | 49.88,35.98 49.88,37.41 | 49.88,37.41
  Bottom 0.2: v34.5,39.19 34.38,39.05 34.73,39.4 34.73,39.51
B$I.25  (via drill 0.2)
  Top 0.15: U.X1.P$N6 35.53,18.42 35.53,19.33 34.81,20.05 v34.84,38.35 | v95.08,25.41 95.98,24.51 95.97,24.51 | v34.84,38.35 34.78,38.36 | 36.53,37.26 35.63,38.36 v34.84,38.35 | 95.97,24.51 95.95,24.53 | 95.97,24.51 96.21,24.28 97.62,24.28 102.73,19.17 U.X2.P$N6 | U.Y.P$N6 31.05,56.96 31.09,57 34.54,57 34.54,56.94 34.53,56.93 v35.4,56.93 | U2.28 78.42,26.23 v79.12,25.53 | v79.11,25.53 v79.12,25.53 | v79.12,25.53 79.13,25.52
  Top 0.17: v49.91,32.96 40.22,32.96 37.35,35.86 36.53,36.68 36.53,37.26 | U.Y.P$N6
  Bottom 0.15: 78.41,26.16 58.66,26.21 | v35.4,56.93 35.26,56.79 35.26,55.47 35.88,54.86 35.82,39.39 35.42,38.99 | 35.42,38.99 35.4,38.97 | 35.43,38.99 35.42,38.99 | 79.29,25.39 79.29,25.4 79.27,25.4 79.26,25.39 v79.12,25.53 | 78.41,26.16 78.49,26.16 v79.12,25.53 | 78.41,26.16 78.46,26.16 78.47,26.17 v79.11,25.53 v79.12,25.53
  Bottom 0.17: v34.84,38.35 35.43,38.99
